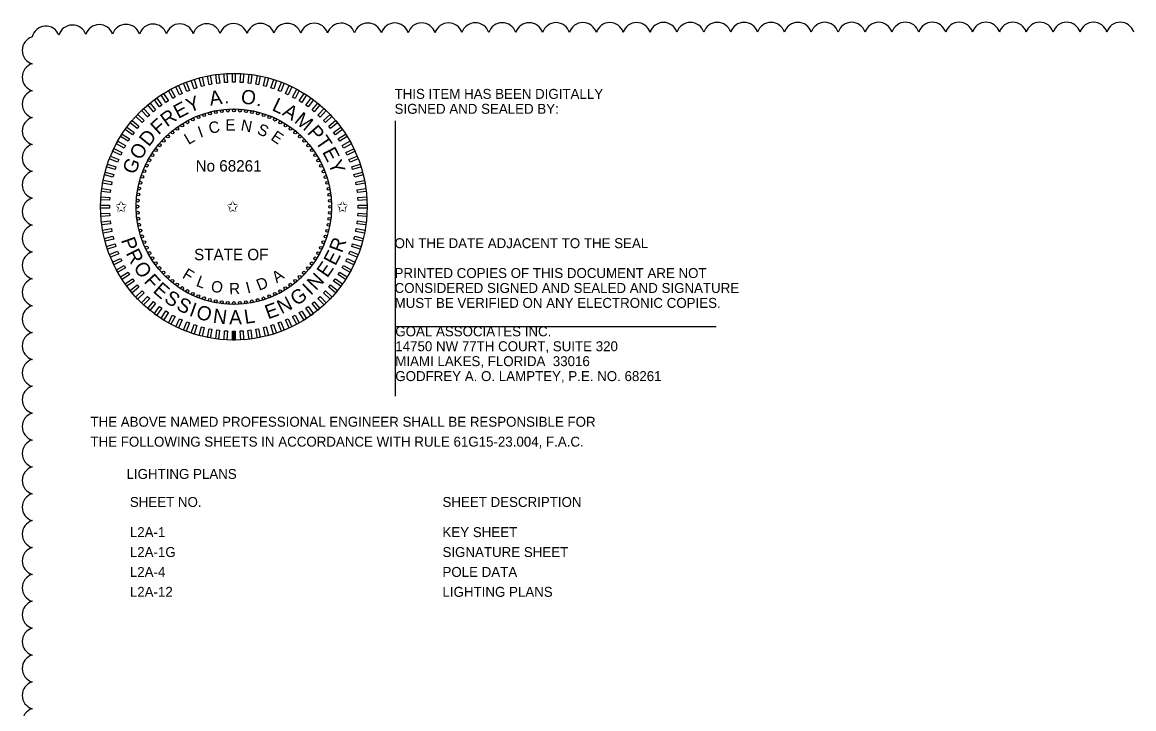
# Model space of a CAD drawing. Extents: x -811 to -790, y -2284 to -2178.
# Drawn here: x -810.98 to -803.16, y -2278.54 to -2273.71 of the extents above; entities that cross this region are included whole.
import ezdxf

# ---------------------------------------------------------------- set-up
doc = ezdxf.new("R2010")
doc.units = 0
for name, color, linetype in [('AdhocPoint_dp', 7, 'Continuous'), ('PlotBorder_dp', 7, 'Continuous'), ('ScratchEle_dp', 7, 'Continuous'), ('TextMinor', 7, 'Continuous'), ('TextMisc', 7, 'Continuous'), ('TextShtNo', 7, 'Continuous')]:
    doc.layers.add(name, color=color, linetype=linetype)

msp = doc.modelspace()

# ---------------------------------------------------------------- linework, layer by layer
at = {"layer": 'AdhocPoint_dp'}
for p, q in [((-808.3546, -2274.4022), (-808.3546, -2276.337)), ((-808.3546, -2275.847), (-806.0979, -2275.847))]:
    msp.add_line(p, q, dxfattribs=at)
at = {"layer": 'ScratchEle_dp'}
for centre, radius, start, end in [((-810.8128, -2273.8348), 0.0992, 21.52097, 166.52097), ((-810.6255, -2273.8267), 0.0991, 18.44241, 163.44241), ((-810.4367, -2273.824), 0.0991, 18.17187, 163.17187), ((-810.2478, -2273.822), 0.0991, 18.03188, 163.03188), ((-810.0588, -2273.8204), 0.0991, 17.94243, 162.94243), ((-809.8699, -2273.819), 0.0991, 17.8789, 162.8789), ((-809.6809, -2273.8179), 0.0991, 17.83076, 162.83076), ((-809.4919, -2273.8168), 0.0991, 17.79266, 162.79266), ((-809.3029, -2273.8159), 0.0991, 17.76151, 162.76151), ((-809.1139, -2273.8151), 0.0991, 17.73544, 162.73544), ((-808.9249, -2273.8144), 0.0991, 17.7132, 162.7132), ((-808.736, -2273.8137), 0.0991, 17.69393, 162.69393), ((-808.547, -2273.8131), 0.0991, 17.67702, 162.67702), ((-808.358, -2273.8125), 0.0991, 17.66204, 162.66204), ((-808.169, -2273.812), 0.0991, 17.64863, 162.64863), ((-807.98, -2273.8115), 0.0991, 17.63655, 162.63655), ((-807.791, -2273.8111), 0.0991, 17.62558, 162.62558), ((-807.602, -2273.8107), 0.0991, 17.61556, 162.61556), ((-807.413, -2273.8104), 0.0991, 17.60637, 162.60637), ((-807.224, -2273.81), 0.0991, 17.5979, 162.5979), ((-807.035, -2273.8097), 0.0991, 17.59006, 162.59006), ((-806.846, -2273.8094), 0.0991, 17.58277, 162.58277), ((-806.657, -2273.8092), 0.0991, 17.57597, 162.57597), ((-806.468, -2273.8089), 0.0991, 17.56961, 162.56961), ((-806.279, -2273.8087), 0.0991, 17.56364, 162.56364), ((-806.09, -2273.8085), 0.0991, 17.55803, 162.55803), ((-805.901, -2273.8083), 0.0991, 17.55274, 162.55274), ((-805.712, -2273.8082), 0.0991, 17.54774, 162.54774), ((-805.523, -2273.808), 0.0991, 17.54301, 162.54301), ((-805.334, -2273.8079), 0.0991, 17.53852, 162.53852), ((-805.145, -2273.8077), 0.0991, 17.53425, 162.53425), ((-804.956, -2273.8076), 0.0991, 17.53018, 162.53018), ((-804.767, -2273.8075), 0.0991, 17.52631, 162.52631), ((-804.578, -2273.8075), 0.0991, 17.52261, 162.52261), ((-804.389, -2273.8074), 0.0991, 17.51907, 162.51907), ((-804.2, -2273.8073), 0.0991, 17.51569, 162.51569), ((-804.011, -2273.8073), 0.0991, 17.51244, 162.51244), ((-803.822, -2273.8073), 0.0991, 17.50933, 162.50933), ((-803.633, -2273.8072), 0.0991, 17.50633, 162.50633), ((-803.444, -2273.8072), 0.0991, 17.50345, 162.50345), ((-803.2551, -2273.8072), 0.0991, 17.50077, 162.50077), ((-810.8794, -2273.9061), 0.099, 107.5, 252.5), ((-810.8794, -2274.095), 0.0991, 107.5, 252.5), ((-810.8794, -2274.2841), 0.0991, 107.5, 252.5), ((-810.8794, -2274.4731), 0.0991, 107.5, 252.5), ((-810.8794, -2274.6621), 0.0991, 107.5, 252.5), ((-810.8794, -2274.8511), 0.0991, 107.5, 252.5), ((-810.8794, -2275.0401), 0.0991, 107.5, 252.5), ((-810.8794, -2275.2291), 0.0991, 107.5, 252.5), ((-810.8794, -2275.4181), 0.0991, 107.5, 252.5), ((-810.8794, -2275.6071), 0.0991, 107.5, 252.5), ((-810.8794, -2275.7961), 0.0991, 107.5, 252.5), ((-810.8794, -2275.9851), 0.0991, 107.5, 252.5), ((-810.8794, -2276.1741), 0.0991, 107.5, 252.5), ((-810.8794, -2276.3631), 0.0991, 107.5, 252.5), ((-810.8794, -2276.5521), 0.0991, 107.5, 252.5), ((-810.8794, -2276.7411), 0.0991, 107.5, 252.5), ((-810.8794, -2276.9301), 0.0991, 107.5, 252.5), ((-810.8794, -2277.1191), 0.0991, 107.5, 252.5), ((-810.8794, -2277.3081), 0.0991, 107.5, 252.5), ((-810.8794, -2277.4971), 0.0991, 107.5, 252.5), ((-810.8794, -2277.6861), 0.0991, 107.5, 252.5), ((-810.8794, -2277.8751), 0.0991, 107.5, 252.5), ((-810.8794, -2278.0641), 0.0991, 107.5, 252.5), ((-810.8794, -2278.2531), 0.0991, 107.5, 252.5), ((-810.8794, -2278.4421), 0.0991, 107.50047, 252.50047), ((-810.8794, -2278.6311), 0.0991, 107.52584, 252.52584)]:
    msp.add_arc(centre, radius, start, end, dxfattribs=at)
at = {"layer": 'TextMinor'}
for radius in [0.9375, 0.6875]:
    msp.add_circle((-809.4901, -2275.0057), radius, dxfattribs=at)
at = {"layer": 'TextShtNo'}
for p, q in [((-809.5001, -2275.9432), (-809.5003, -2275.8807)), ((-809.4901, -2275.9432), (-809.4903, -2275.8807)), ((-809.4801, -2275.9431), (-809.4803, -2275.8806))]:
    msp.add_line(p, q, dxfattribs=at)
for points in [[(-809.6441, -2274.1442), (-809.6639, -2274.148), (-809.6756, -2274.0867), (-809.6558, -2274.0829)], [(-809.5897, -2274.1362), (-809.6097, -2274.1388), (-809.6175, -2274.0768), (-809.5975, -2274.0743)], [(-809.5349, -2274.1317), (-809.555, -2274.133), (-809.559, -2274.0707), (-809.5388, -2274.0694)], [(-809.4799, -2274.1306), (-809.5001, -2274.1306), (-809.5001, -2274.0682), (-809.4799, -2274.0682)], [(-809.425, -2274.133), (-809.4452, -2274.1317), (-809.4412, -2274.0694), (-809.4211, -2274.0707)], [(-809.3703, -2274.1388), (-809.3904, -2274.1363), (-809.3825, -2274.0743), (-809.3625, -2274.0768)], [(-809.3161, -2274.148), (-809.336, -2274.1442), (-809.3243, -2274.0829), (-809.3044, -2274.0867)], [(-809.8535, -2274.2096), (-809.8717, -2274.2182), (-809.8983, -2274.1617), (-809.8801, -2274.1531)], [(-809.8028, -2274.1883), (-809.8215, -2274.1957), (-809.8445, -2274.1377), (-809.8258, -2274.1303)], [(-809.7508, -2274.1703), (-809.77, -2274.1765), (-809.7893, -2274.1172), (-809.7701, -2274.1109)], [(-809.6979, -2274.1556), (-809.7174, -2274.1606), (-809.7329, -2274.1001), (-809.7134, -2274.0951)], [(-809.2626, -2274.1606), (-809.2822, -2274.1556), (-809.2667, -2274.0951), (-809.2471, -2274.1002)], [(-809.21, -2274.1766), (-809.2292, -2274.1704), (-809.2099, -2274.111), (-809.1907, -2274.1172)], [(-809.1585, -2274.1958), (-809.1773, -2274.1884), (-809.1543, -2274.1303), (-809.1355, -2274.1378)], [(-809.1083, -2274.2182), (-809.1266, -2274.2096), (-809.1, -2274.1531), (-809.0817, -2274.1617)], [(-809.9504, -2274.2614), (-809.9674, -2274.2722), (-810.0009, -2274.2195), (-809.9838, -2274.2087)], [(-809.9027, -2274.2339), (-809.9204, -2274.2437), (-809.9505, -2274.189), (-809.9328, -2274.1792)], [(-809.0596, -2274.2438), (-809.0773, -2274.234), (-809.0473, -2274.1793), (-809.0296, -2274.189)], [(-809.0127, -2274.2723), (-809.0297, -2274.2615), (-808.9962, -2274.2088), (-808.9792, -2274.2196)], [(-810.0817, -2274.3608), (-810.0964, -2274.3746), (-810.1391, -2274.3291), (-810.1244, -2274.3153)], [(-810.04, -2274.3249), (-810.0556, -2274.3378), (-810.0954, -2274.2897), (-810.0798, -2274.2768)], [(-809.9962, -2274.2917), (-810.0125, -2274.3036), (-810.0492, -2274.2531), (-810.0329, -2274.2412)], [(-808.9675, -2274.3037), (-808.9839, -2274.2919), (-808.9472, -2274.2413), (-808.9308, -2274.2532)], [(-808.9245, -2274.3379), (-808.9401, -2274.3251), (-808.9003, -2274.2769), (-808.8847, -2274.2898)], [(-808.8837, -2274.3748), (-808.8984, -2274.3609), (-808.8557, -2274.3154), (-808.8409, -2274.3292)], [(-810.121, -2274.3992), (-810.1348, -2274.4139), (-810.1803, -2274.3712), (-810.1665, -2274.3565)], [(-808.8453, -2274.4141), (-808.8591, -2274.3994), (-808.8136, -2274.3566), (-808.7998, -2274.3713)], [(-810.192, -2274.4831), (-810.2039, -2274.4994), (-810.2544, -2274.4627), (-810.2426, -2274.4464)], [(-810.1578, -2274.44), (-810.1707, -2274.4556), (-810.2188, -2274.4158), (-810.206, -2274.4002)], [(-808.8094, -2274.4557), (-808.8223, -2274.4402), (-808.7742, -2274.4004), (-808.7613, -2274.4159)], [(-808.7762, -2274.4996), (-808.7881, -2274.4832), (-808.7376, -2274.4465), (-808.7257, -2274.4629)], [(-810.252, -2274.5752), (-810.2617, -2274.5929), (-810.3164, -2274.5628), (-810.3067, -2274.5451)], [(-810.2235, -2274.5282), (-810.2343, -2274.5452), (-810.287, -2274.5118), (-810.2762, -2274.4947)], [(-808.7458, -2274.5454), (-808.7567, -2274.5283), (-808.7039, -2274.4949), (-808.6931, -2274.5119)], [(-808.7184, -2274.593), (-808.7281, -2274.5753), (-808.6734, -2274.5453), (-808.6637, -2274.5629)], [(-810.2775, -2274.6239), (-810.2861, -2274.6421), (-810.3426, -2274.6155), (-810.334, -2274.5973)], [(-808.694, -2274.6423), (-808.7026, -2274.624), (-808.6461, -2274.5974), (-808.6375, -2274.6157)], [(-810.3192, -2274.7256), (-810.3254, -2274.7448), (-810.3848, -2274.7255), (-810.3786, -2274.7063)], [(-810.3, -2274.6741), (-810.3074, -2274.6928), (-810.3654, -2274.6698), (-810.358, -2274.6511)], [(-808.6728, -2274.693), (-808.6802, -2274.6742), (-808.6222, -2274.6512), (-808.6147, -2274.67)], [(-808.6548, -2274.7449), (-808.661, -2274.7257), (-808.6016, -2274.7064), (-808.5954, -2274.7256)], [(-810.3351, -2274.7782), (-810.3401, -2274.7977), (-810.4006, -2274.7822), (-810.3956, -2274.7626)], [(-808.64, -2274.7979), (-808.6451, -2274.7784), (-808.5846, -2274.7628), (-808.5796, -2274.7824)], [(-810.3477, -2274.8317), (-810.3515, -2274.8515), (-810.4129, -2274.8398), (-810.4091, -2274.82)], [(-808.6287, -2274.8517), (-808.6325, -2274.8319), (-808.5711, -2274.8202), (-808.5673, -2274.84)], [(-810.3628, -2274.9405), (-810.364, -2274.9607), (-810.4264, -2274.9568), (-810.4251, -2274.9366)], [(-810.357, -2274.8859), (-810.3595, -2274.9059), (-810.4214, -2274.8981), (-810.4189, -2274.878)], [(-808.6207, -2274.9061), (-808.6232, -2274.8861), (-808.5613, -2274.8782), (-808.5588, -2274.8983)], [(-808.6162, -2274.9609), (-808.6174, -2274.9407), (-808.5551, -2274.9368), (-808.5539, -2274.957)], [(-810.3651, -2274.9955), (-810.3651, -2275.0156), (-810.4276, -2275.0156), (-810.4276, -2274.9955)], [(-808.6151, -2275.0158), (-808.6151, -2274.9957), (-808.5526, -2274.9957), (-808.5526, -2275.0158)], [(-810.3641, -2275.0504), (-810.3628, -2275.0706), (-810.4251, -2275.0745), (-810.4264, -2275.0543)], [(-808.6175, -2275.0708), (-808.6162, -2275.0506), (-808.5539, -2275.0545), (-808.5551, -2275.0747)], [(-810.3595, -2275.1052), (-810.357, -2275.1252), (-810.4189, -2275.1331), (-810.4215, -2275.113)], [(-810.3516, -2275.1596), (-810.3478, -2275.1794), (-810.4091, -2275.1911), (-810.4129, -2275.1713)], [(-808.6325, -2275.1796), (-808.6287, -2275.1598), (-808.5674, -2275.1715), (-808.5712, -2275.1913)], [(-808.6233, -2275.1254), (-808.6207, -2275.1054), (-808.5588, -2275.1132), (-808.5613, -2275.1333)], [(-810.3402, -2275.2134), (-810.3352, -2275.2329), (-810.3956, -2275.2485), (-810.4007, -2275.2289)], [(-808.6451, -2275.2331), (-808.6401, -2275.2136), (-808.5796, -2275.2291), (-808.5846, -2275.2487)], [(-810.3255, -2275.2664), (-810.3192, -2275.2856), (-810.3786, -2275.3049), (-810.3849, -2275.2857)], [(-810.3074, -2275.3183), (-810.3, -2275.3371), (-810.3581, -2275.3601), (-810.3655, -2275.3413)], [(-808.6803, -2275.3372), (-808.6729, -2275.3185), (-808.6148, -2275.3415), (-808.6222, -2275.3602)], [(-808.6611, -2275.2857), (-808.6548, -2275.2665), (-808.5954, -2275.2858), (-808.6017, -2275.305)], [(-810.2862, -2275.369), (-810.2776, -2275.3873), (-810.3341, -2275.4139), (-810.3427, -2275.3956)], [(-808.7027, -2275.3874), (-808.6941, -2275.3692), (-808.6376, -2275.3958), (-808.6462, -2275.414)], [(-810.2618, -2275.4183), (-810.2521, -2275.436), (-810.3068, -2275.466), (-810.3165, -2275.4484)], [(-810.2344, -2275.4659), (-810.2236, -2275.483), (-810.2763, -2275.5164), (-810.2871, -2275.4994)], [(-808.7568, -2275.4831), (-808.7459, -2275.4661), (-808.6932, -2275.4995), (-808.704, -2275.5166)], [(-808.7282, -2275.4361), (-808.7185, -2275.4184), (-808.6638, -2275.4485), (-808.6735, -2275.4662)], [(-810.204, -2275.5117), (-810.1922, -2275.5281), (-810.2427, -2275.5648), (-810.2545, -2275.5484)], [(-810.1708, -2275.5556), (-810.158, -2275.5711), (-810.2061, -2275.6109), (-810.2189, -2275.5954)], [(-808.8224, -2275.5713), (-808.8095, -2275.5557), (-808.7614, -2275.5955), (-808.7743, -2275.6111)], [(-808.7882, -2275.5282), (-808.7763, -2275.5119), (-808.7258, -2275.5486), (-808.7377, -2275.5649)], [(-810.135, -2275.5972), (-810.1211, -2275.6119), (-810.1667, -2275.6547), (-810.1805, -2275.64)], [(-810.0965, -2275.6365), (-810.0818, -2275.6504), (-810.1246, -2275.6959), (-810.1393, -2275.6821)], [(-808.8985, -2275.6505), (-808.8838, -2275.6367), (-808.8411, -2275.6822), (-808.8558, -2275.696)], [(-808.8592, -2275.6121), (-808.8454, -2275.5974), (-808.7999, -2275.6401), (-808.8137, -2275.6548)], [(-810.0557, -2275.6734), (-810.0402, -2275.6862), (-810.08, -2275.7344), (-810.0955, -2275.7215)], [(-810.0127, -2275.7076), (-809.9964, -2275.7194), (-810.0331, -2275.77), (-810.0494, -2275.7581)], [(-808.984, -2275.7196), (-808.9677, -2275.7077), (-808.931, -2275.7582), (-808.9473, -2275.7701)], [(-808.9402, -2275.6864), (-808.9246, -2275.6735), (-808.8848, -2275.7216), (-808.9004, -2275.7345)], [(-809.9676, -2275.739), (-809.9505, -2275.7498), (-809.984, -2275.8025), (-810.001, -2275.7917)], [(-809.9206, -2275.7675), (-809.9029, -2275.7773), (-809.933, -2275.832), (-809.9507, -2275.8223)], [(-809.8719, -2275.7931), (-809.8536, -2275.8017), (-809.8802, -2275.8582), (-809.8985, -2275.8496)], [(-809.1268, -2275.8017), (-809.1085, -2275.7931), (-809.0819, -2275.8496), (-809.1002, -2275.8582)], [(-809.0775, -2275.7774), (-809.0598, -2275.7676), (-809.0297, -2275.8223), (-809.0474, -2275.8321)], [(-809.0299, -2275.7499), (-809.0128, -2275.7391), (-808.9794, -2275.7918), (-808.9964, -2275.8026)], [(-809.8217, -2275.8155), (-809.8029, -2275.8229), (-809.8259, -2275.881), (-809.8447, -2275.8735)], [(-809.7702, -2275.8347), (-809.751, -2275.8409), (-809.7703, -2275.9003), (-809.7895, -2275.8941)], [(-809.7176, -2275.8507), (-809.698, -2275.8557), (-809.7136, -2275.9162), (-809.7331, -2275.9111)], [(-809.6641, -2275.8633), (-809.6443, -2275.8671), (-809.656, -2275.9284), (-809.6758, -2275.9246)], [(-809.6099, -2275.8725), (-809.5899, -2275.875), (-809.5977, -2275.937), (-809.6177, -2275.9345)], [(-809.5552, -2275.8783), (-809.5351, -2275.8796), (-809.539, -2275.9419), (-809.5591, -2275.9406)], [(-809.5003, -2275.8807), (-809.4801, -2275.8807), (-809.4801, -2275.9431), (-809.5003, -2275.9431)], [(-809.4453, -2275.8796), (-809.4252, -2275.8783), (-809.4213, -2275.9406), (-809.4414, -2275.9419)], [(-809.3906, -2275.8751), (-809.3705, -2275.8725), (-809.3627, -2275.9345), (-809.3827, -2275.937)], [(-809.3362, -2275.8671), (-809.3163, -2275.8633), (-809.3046, -2275.9246), (-809.3245, -2275.9284)], [(-809.2824, -2275.8557), (-809.2628, -2275.8507), (-809.2473, -2275.9112), (-809.2668, -2275.9162)], [(-809.2294, -2275.841), (-809.2102, -2275.8348), (-809.1909, -2275.8941), (-809.2101, -2275.9004)], [(-809.1775, -2275.823), (-809.1587, -2275.8156), (-809.1357, -2275.8736), (-809.1545, -2275.881)]]:
    msp.add_lwpolyline(points, close=True, dxfattribs=at)
for centre in [(-809.7781, -2274.3924), (-809.739, -2274.3755), (-809.6989, -2274.3612), (-809.6581, -2274.3493), (-809.6165, -2274.3401), (-809.5745, -2274.3335), (-809.5321, -2274.3295), (-809.4896, -2274.3282), (-809.447, -2274.3296), (-809.4046, -2274.3336), (-809.3626, -2274.3403), (-809.3211, -2274.3496), (-809.2802, -2274.3615), (-809.2402, -2274.376), (-809.2012, -2274.3929), (-809.9215, -2274.4833), (-809.8879, -2274.4572), (-809.8526, -2274.4333), (-809.816, -2274.4117), (-809.1633, -2274.4123), (-809.1266, -2274.4339), (-809.0915, -2274.4579), (-809.0578, -2274.484), (-809.9836, -2274.5415), (-809.9535, -2274.5114), (-809.0259, -2274.5122), (-808.9959, -2274.5423), (-810.0379, -2274.607), (-810.0118, -2274.5734), (-808.9678, -2274.5742), (-808.9417, -2274.6079), (-810.1029, -2274.7167), (-810.0835, -2274.6788), (-810.0618, -2274.6422), (-808.9178, -2274.6431), (-808.8962, -2274.6798), (-808.8769, -2274.7177), (-810.1343, -2274.7958), (-810.1198, -2274.7557), (-808.86, -2274.7568), (-808.8456, -2274.7968), (-810.1462, -2274.8366), (-808.8338, -2274.8377), (-810.1622, -2274.9202), (-810.1555, -2274.8782), (-808.8245, -2274.8793), (-808.8179, -2274.9213), (-810.1676, -2275.0051), (-810.1662, -2274.9625), (-808.814, -2274.9637), (-808.8126, -2275.0062), (-810.1663, -2275.0476), (-810.1623, -2275.09), (-808.8181, -2275.0911), (-808.814, -2275.0488), (-810.1557, -2275.132), (-810.1464, -2275.1736), (-808.8341, -2275.1747), (-808.8248, -2275.1331), (-810.1346, -2275.2145), (-810.1202, -2275.2545), (-808.8604, -2275.2556), (-808.846, -2275.2155), (-810.1033, -2275.2936), (-810.0841, -2275.3315), (-808.8967, -2275.3325), (-808.8774, -2275.2946), (-810.0624, -2275.3682), (-810.0385, -2275.4034), (-808.9424, -2275.4043), (-808.9184, -2275.3691), (-810.0125, -2275.4371), (-809.9844, -2275.469), (-809.9543, -2275.4991), (-809.0268, -2275.4999), (-808.9967, -2275.4698), (-808.9685, -2275.4379), (-809.9224, -2275.5273), (-809.8888, -2275.5534), (-809.8536, -2275.5774), (-809.1276, -2275.578), (-809.0924, -2275.5541), (-809.0587, -2275.528), (-809.817, -2275.599), (-809.7791, -2275.6184), (-809.74, -2275.6353), (-809.7, -2275.6498), (-809.2813, -2275.6501), (-809.2412, -2275.6358), (-809.2022, -2275.6189), (-809.1642, -2275.5996), (-809.6591, -2275.6617), (-809.6176, -2275.671), (-809.5756, -2275.6777), (-809.5332, -2275.6817), (-809.4901, -2275.6832), (-809.4481, -2275.6818), (-809.4058, -2275.6778), (-809.3637, -2275.6712), (-809.3222, -2275.662)]:
    msp.add_circle(centre, 0.01, dxfattribs=at)

# ---------------------------------------------------------------- texts
at = {"layer": 'PlotBorder_dp'}
for s, p in [('THIS ITEM HAS BEEN DIGITALLY', (-808.3596, -2274.2471)), ('SIGNED AND SEALED BY:', (-808.3596, -2274.3521)), ('ON THE DATE ADJACENT TO THE SEAL', (-808.3596, -2275.2971)), ('PRINTED COPIES OF THIS DOCUMENT ARE NOT ', (-808.3596, -2275.5071)), ('CONSIDERED SIGNED AND SEALED AND SIGNATURE ', (-808.3596, -2275.6121)), ('MUST BE VERIFIED ON ANY ELECTRONIC COPIES.', (-808.3596, -2275.7171)), ('GOAL ASSOCIATES INC.', (-808.3546, -2275.917)), ('14750 NW 77TH COURT, SUITE 320', (-808.3546, -2276.022)), ('MIAMI LAKES, FLORIDA  33016', (-808.3546, -2276.127)), ('GODFREY A. O. LAMPTEY, P.E. NO. 68261', (-808.3546, -2276.232)), ('THE ABOVE NAMED PROFESSIONAL ENGINEER SHALL BE RESPONSIBLE FOR ', (-810.4987, -2276.5531)), ('THE FOLLOWING SHEETS IN ACCORDANCE WITH RULE 61G15-23.004, F.A.C.', (-810.4987, -2276.6931)), ('LIGHTING PLANS', (-810.245, -2276.9201))]:
    msp.add_text(s, height=0.07, dxfattribs=at).set_placement(p)
at = {"layer": 'TextMisc'}
for s, p in [('SHEET NO.', (-810.2215, -2277.1171)), ('SHEET DESCRIPTION', (-808.0226, -2277.1171)), ('L2A-1', (-810.2215, -2277.3293)), ('KEY SHEET', (-808.0226, -2277.3293)), ('L2A-1G', (-810.2215, -2277.4693)), ('SIGNATURE SHEET', (-808.0226, -2277.4693)), ('L2A-4', (-810.2215, -2277.6093)), ('POLE DATA', (-808.0226, -2277.6093)), ('L2A-12', (-810.2215, -2277.7493)), ('LIGHTING PLANS', (-808.0226, -2277.7493))]:
    msp.add_text(s, height=0.07, dxfattribs=at).set_placement(p)
at = {"layer": 'TextShtNo'}
for s, height, rotation, p in [('Y', 0.1, 21.06329, (-809.8021, -2274.3462)), ('A', 0.1, 8.80884, (-809.6551, -2274.295)), ('O', 0.1, 352.18771, (-809.4449, -2274.2775)), ('L', 0.1, 334.67271, (-809.2279, -2274.3249)), ('E', 0.1, 28.10553, (-809.8806, -2274.3895)), ('.', 0.1, 1.04184, (-809.5575, -2274.2793)), ('.', 0.1, 343.52684, (-809.3358, -2274.2926)), ('A', 0.1, 328.40959, (-809.1552, -2274.3576)), ('F', 0.1, 42.37723, (-810.0205, -2274.5047)), ('R', 0.1, 35.92688, (-809.9609, -2274.4483)), ('E', 0.08, 0.41861, (-809.5498, -2274.4706)), ('N', 0.08, 349.29143, (-809.4455, -2274.4691)), ('M', 0.1, 320.6426, (-809.0707, -2274.4088)), ('D', 0.1, 50.8569, (-810.0885, -2274.5884)), ('I', 0.08, 20.01168, (-809.7258, -2274.5216)), ('C', 0.08, 12.20255, (-809.6579, -2274.494)), ('S', 0.08, 337.02207, (-809.3325, -2274.4909)), ('E', 0.08, 325.86633, (-809.2358, -2274.5311)), ('P', 0.1, 311.19658, (-808.9784, -2274.4857)), ('L', 0.08, 30.40215, (-809.8093, -2274.572)), ('T', 0.1, 304.45632, (-808.9209, -2274.5494)), ('O', 0.1, 59.51777, (-810.1446, -2274.6833)), ('E', 0.1, 297.63152, (-808.8707, -2274.6202)), ('G', 0.1, 68.0518, (-810.1851, -2274.784)), ('Y', 0.1, 290.58928, (-808.8281, -2274.6991)), ('P', 0.1, 289.40551, (-810.2848, -2275.2402)), ('R', 0.1, 69.5134, (-808.7299, -2275.3354)), ('R', 0.1, 296.14576, (-810.2518, -2275.3319)), ('E', 0.1, 62.47116, (-808.7761, -2275.4261)), ('O', 0.1, 303.96711, (-810.2003, -2275.4325)), ('E', 0.1, 55.42892, (-808.833, -2275.5104)), ('F', 0.1, 312.62798, (-810.1279, -2275.5346)), ('F', 0.08, 328.72408, (-809.8582, -2275.5022)), ('L', 0.08, 339.29159, (-809.7609, -2275.5613)), ('A', 0.08, 34.49917, (-809.1883, -2275.5451)), ('N', 0.1, 47.17876, (-808.9123, -2275.5995)), ('E', 0.1, 319.07833, (-810.0645, -2275.6029)), ('O', 0.08, 349.68206, (-809.6562, -2275.601)), ('R', 0.08, 2.33977, (-809.5217, -2275.623)), ('I', 0.08, 14.20366, (-809.3941, -2275.6163)), ('D', 0.08, 22.01279, (-809.312, -2275.5976)), ('I', 0.1, 43.64556, (-808.9499, -2275.634)), ('S', 0.1, 326.12056, (-809.9869, -2275.6688)), ('N', 0.1, 26.86136, (-809.1544, -2275.7632)), ('G', 0.1, 35.11153, (-809.0492, -2275.7072)), ('S', 0.1, 333.193, (-809.9015, -2275.7249)), ('I', 0.1, 340.26543, (-809.8098, -2275.7701)), ('O', 0.1, 343.79863, (-809.7621, -2275.7883)), ('N', 0.1, 352.45949, (-809.6411, -2275.8204)), ('E', 0.1, 19.81912, (-809.2498, -2275.7986)), ('A', 0.1, 0.70966, (-809.5227, -2275.8336)), ('L', 0.1, 8.47665, (-809.4105, -2275.8304))]:
    msp.add_text(s, height=height, rotation=rotation, dxfattribs=at).set_placement(p)
for s, p in [('No 68261', (-809.7591, -2274.7584)), ('✩', (-810.3251, -2275.0436)), ('✩', (-809.5404, -2275.0436)), ('✩', (-808.7685, -2275.0436)), ('STATE OF', (-809.7698, -2275.3818))]:
    msp.add_text(s, height=0.08, dxfattribs=at).set_placement(p)

doc.saveas('drawing.dxf')
